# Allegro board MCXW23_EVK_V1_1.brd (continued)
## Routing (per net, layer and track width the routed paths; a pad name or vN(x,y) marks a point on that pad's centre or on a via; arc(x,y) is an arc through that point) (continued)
P5VA: length 15.1
  TOP w0.2: 14,41.54 L6.1 13.41,40.95
  TOP w0.25: v1(32.5,55) C64.1 31.74,56.2 31.44,56.5 C65.1 30,56.5 29.48,55.98 U19.8 ; R66.2 v1(43.75,71) ; U17.5 37.9,60.15 38.45,60.7 C61.1 v1(39.25,59.75) ; L6.1 14.49,40.95 15.04,41.5 C54.1 ; R72.2 v1(43.75,67)
  IN2 w0.5: v1(39.25,59.75) 38.25,60.75
  vias: v1(13.75,42.25) v1(14.75,42.25)
VBAT_DCDC/VBAT_PMU: length 15.1
  TOP w0.2: C37.1 60.09,19.3 ; C37.1 58.41,19.3 ; C37.1 59.25,20.04 ; 57.75,19.64 C36.1 58.37,19 ; 57,20 56.75,20 56.75,19.5 ; 56,20.25 U9.49 56,22.25 56.74,22.99 ; 56.75,23 56.74,22.99 ; 56.74,22.99 U9.51 ; 60.31,19.22 L2.2 61,19.94 ; U9.50 56.99,21.27 ; U9.50 56.51,20.2 ; U9.50 56.51,22.34 ; U9.51 59.3,22.99 ; U9.51 58.23,22.51
  TOP w0.25: C35.1 56.75,19.5
VBUS: length 144.4
  TOP w0.2: U11.3 30.45,11.49 ; U11.3 30.45,9.81 ; U11.3 31.07,10.65 ; 17.01,75.05 U30.1 ; U30.1 17.85,74.43 ; U30.1 18.69,75.05 ; U30.3 17.85,77.57 ; U30.3 17.01,76.95 ; U30.3 18.69,76.95 ; 18.04,79 C90.2 17.3,78.16 ; D18.A 22.43,9.5 ; D18.A 21.64,8.56 ; D18.A 20.85,9.5 ; D18.A 21.64,10.44 ; 30.5,9.29 BD1.2 29.66,8.55 ; 27.66,8.55 C50.2 ; C50.2 29.34,8.55 ; C50.2 28.5,9.29 ; 27.93,10.65 U11.1 ; U11.1 28.55,9.81 ; U11.1 28.55,11.49
  TOP w0.25: R63.1 v1(48,15.5)
  BOTTOM w0.5: v1(19.5,79) v1(18.5,79) 16.5,79 13.75,76.25 13.75,46.5 3,35.75 3,11.74 6.24,8.5 v1(23.5,8.5) v1(24.75,8.5) v1(26,8.5) v1(27.25,8.5) 41.14,8.5 48,15.36 v1(48,15.5)
VCC_IF_LINK: length 109.9
  TOP w0.25: U28.6 73.1,95.19 73,95.09 C81.1 72.5,94.5 72,95 v1(72,95.75) ; v1(68,95.75) 68,95 68.5,94.5 C74.1 69,95.06 69.1,95.16 U25.6 ; R104.1 v1(69,100.5) ; U27.6 65.1,95.16 65,95.06 C78.1 64.48,94.5 64,94.98 v1(64,95.75) ; v1(71.75,100.5) 71.75,99.76 72.01,99.5 R112.1 ; L7.1 v1(59,95.75) ; C77.1 61,94.52 ; 61,94.52 60.25,94.52 60,94.77 v1(60,95.75) ; 61,94.52 61,95.06 61.1,95.16 U26.6 ; R42.1 v1(31.5,42.25) ; v1(42,85.5) v1(42,75) ; R108.1 v1(65,100.5)
  BOTTOM w0.25: v1(42,85.5) 42.75,85.5 43.5,84.75 45.5,84.75 47.5,86.75 47.5,90.68 48.82,92 57,92 57.25,91.75 59.26,91.75 60,92.49 v1(60,95.75) ; v1(31.5,42.25) 31.5,50.49 41.5,60.49 41.5,74.5 v1(42,75)
VCC_MIKROE: length 109.2
  TOP w0.25: R30.1 v1(86,77.25) ; R29.1 v1(86,38.25) ; 86,108.12 R37.1
  TOP w0.5: v1(86,107.5) 86,108.12
  IN2 w0.5: v1(86,38.25) 82.75,41.5 82.75,46.51 80.5,48.76 80.5,54 ; v1(86,107.5) 87.25,106.25 87.25,96.5 83.25,92.5 83.25,80 v1(86,77.25) 86,74 84.5,72.5 84.5,61.62 83.25,60.37 83.25,56.75 80.5,54 ; 80.5,54 60.23,54 v2(56.49,57.74)
  BOTTOM w0.5: v2(56.49,57.74) 56.49,58.81 56.5,58.82 J16.2
ADC0_CH1_CURR: length 64.5
  TOP w0.25: TP7.1 R82.2 27.7,48.24 28,47.94 R84.2 C66.1 28,45.96 28.5,45.46 28.5,43.88 ; U9.57 v1(56.75,26) ; v1(45.75,28.5) U9.14 ; 28.5,43.88 30.25,42.13 30.25,37.24 27.25,34.24 v1(27.25,30.5) ; 28.5,43.88 28.47,43.85 U20.E 26.18,43.85 25.56,43.23 J35.1
  BOTTOM w0.25: v1(27.25,30.5) 28.25,30.5 29,29.75 37.85,29.75 38.13,30.03 38.13,30.25 38.63,30.75 41.75,30.75 44,28.5 v1(45.75,28.5) 48.25,26 v1(56.75,26)
ADC1_CH1_V: length 56.5
  TOP w0.25: v1(27.75,28.25) 27.75,28.75 28,29 28,31.75 27.75,32 27.75,34 30.75,37 30.75,42.46 31.25,42.96 31.25,49.01 36.5,54.26 36.5,55.51 36.64,55.65 U18.E 37.45,56.05 37,56.5 C63.1 37,57.54 37.3,57.84 R76.2 TP3.1 ; v1(44.25,25.75) 44,25.75 43.75,25.5 U9.20
  BOTTOM w0.25: v1(44.25,25.75) 42.5,27.5 40.5,27.5 40.25,27.25 35.75,27.25 34.75,28.25 v1(27.75,28.25)
ARD_D2: length 2.6
  TOP w0.2: R125.1 95,48.94 94.84,49.1 J26.3
ARD_D18: length 4.1
  TOP w0.25: R126.2 95,4.92 J25.5
ARD_D19: length 4.9
  TOP w0.25: J25.6 97.96,4.5 97.25,4.5 96.75,5 R127.2
ARD_IIC_SCK: length 2.6
  TOP w0.25: J24.10 55.22,49.74 55.5,49.46 R116.1
ARD_IIC_SDA: length 2.6
  TOP w0.25: R118.1 58,48.96 57.76,49.2 J24.9
ARD_RXD: length 2.5
  TOP w0.2: R124.1 100,48.94 99.92,49.02 J26.1
ARD_SPI_LIFO: length 2.5
  TOP w0.25: J24.5 67.92,49.74 68,49.66 R120.1
ARD_SPI_LOFI: length 2.5
  TOP w0.25: J24.4 70.46,49.74 70.5,49.7 R121.1
ARD_SPI_SCK: length 2.5
  TOP w0.25: R119.1 65.5,49.62 65.38,49.74 J24.6
ARD_SPI_SS: length 2.5
  TOP w0.25: J24.3 R122.1
ARD_TXD: length 2.5
  TOP w0.2: J26.2 97.38,49.06 97.5,48.94 R123.1
BRG_I2C0_SCL: length 45.2
  TOP w0.25: v1(48.25,68.25) 48.25,66 49.75,64.5 49.75,46.75 53.75,42.75 58,42.75 58.25,42.5 58.25,37.74 57.24,36.73 U9.76 ; v1(51.75,68.25) 52,68 R101.2 53.52,68 53.61,68.09 U24.5
  BOTTOM w0.25: v1(48.25,68.25) v1(51.75,68.25)
BRG_I2C0_SDA: length 44.1
  TOP w0.25: v1(51.75,70.75) 52,71 R102.2 53.29,71 53.38,70.91 U24.4 ; U9.86 51.5,37.75 49.25,40 49.25,44.25 47.75,45.75 47.75,63.5 46,65.25 46,70.25 v1(46.5,70.75)
  BOTTOM w0.25: v1(46.5,70.75) v1(51.75,70.75)
BRG_SPI1_MISO: length 68.7
  TOP w0.25: U22.12 56.25,73 57.5,71.75 57.5,64.25 57,63.75 55.5,63.75 55.25,63.5 55.25,56.49 53.25,54.49 53.25,49.5 54.5,48.25 54.5,46.41 55.16,45.75 61.74,45.75 67.5,39.99 67.5,39.76 67.76,39.5 67.76,31.92 65.08,29.24 60.49,29.24 59.75,28.5 U9.62
BRG_SPI1_MOSI: length 64.3
  TOP w0.25: U9.60 60.25,27.5 61,28.25 65.5,28.25 68.75,31.5 68.75,40.24 61.5,47.49 v1(61.5,52) ; v1(58,52.25) 58,72 56.75,73.25 U22.13
  BOTTOM w0.25: v1(58,52.25) 60.64,52.25 60.89,52 v1(61.5,52)
BRG_SPI1_SCLK: length 61.1
  TOP w0.25: U22.14 57.25,73.5 58.5,72.25 58.5,54.76 59,54.26 59,49.25 68.25,40 68.25,31.71 65.29,28.75 60.75,28.75 60,28 U9.61
BRG_SPI1_SSEL: length 49.8
  TOP w0.25: v1(53.5,48) 52.75,48.75 52.75,54.75 54.75,56.75 54.75,63.75 55.32,64.32 56.75,64.32 57,64.57 57,71.5 55.75,72.75 U22.11 ; v1(59,42.25) 59,37.5 57,35.5 57,34.75 57.25,34.5 U9.74
  BOTTOM w0.25: v1(53.5,48) 54.5,47 54.5,46.75 v1(59,42.25)
CTRL_CAL_DISC: length 41.7
  TOP w0.2: 42.23,68.98 42.44,68.98 42.46,69
  TOP w0.25: U9.3 43.75,34 44,34.25 44,35.24 43.25,35.99 43.25,39.75 44.66,41.16 44.66,55.85 42.51,58 41.5,58 v1(40.75,58.75) ; 43,69 R227.2 ; R227.2 v1(42.75,68) ; R227.2 42.25,69 42.23,68.98 Q21.G
  BOTTOM w0.25: v1(42.75,68) 42,67.25 42,60 v1(40.75,58.75)
CTRL_CAL_R1: length 76.3
  TOP w0.25: v1(51.5,22.75) 52,22.25 U9.41 ; v1(21,18.5) 20.25,19.25 20.25,58.75 20,59 19.98,59 19.88,59.1 D20.C
  BOTTOM w0.25: v1(21,18.5) 21.75,17.75 37.25,17.75 39.24,19.74 46.25,19.74 47.26,20.75 49.5,20.75 v1(51.5,22.75)
CTRL_CAL_R2: length 82.1
  TOP w0.25: U9.42 v1(52.5,22.75) ; Q17.G 18.52,62.98 20.75,60.75 20.75,19.75 v1(22,18.5)
  BOTTOM w0.25: v1(52.5,22.75) 51.5,23.75 49.58,23.75 49.25,23.42 49.25,22.4 48.1,21.25 47,21.25 46,20.25 38.99,20.25 37.24,18.5 v1(22,18.5)
CTRL_HIGH_CURR: length 61
  TOP w0.25: 42.75,63.75 R74.1 42.44,65 42.42,64.98 Q8.G ; 42.75,63.75 42.75,62.25 42.7,62.2 ; 42.75,63.75 v1(40.75,63.75) ; v1(34.5,63.75) 34.5,64.78 34.3,64.98 Q14.G ; U9.22 45,24.5 46.5,26 46.5,30.25 45,31.75 45,35 45.5,35.5 47.25,35.5 47.5,35.75 U9.94 47.5,37.72 47.73,37.95 47.73,42.27 45.75,44.25 45.75,56.24 43.43,58.56 43.43,59.03 42.75,59.71 42.75,62.15 42.7,62.2 ; 42.7,62.2 U16.4
  BOTTOM w0.25: v1(40.75,63.75) v1(34.5,63.75)
CTRL_HIGH_CURR_DIS: length 29.1
  TOP w0.25: U9.92 48.5,38 48.25,38.25 48.25,42.49 46.25,44.49 46.25,56.5 45.25,57.5 v1(45.25,58.75) ; U16.6 41.55,59.63 41.75,59.43 v1(41.75,58.75)
  BOTTOM w0.25: v1(45.25,58.75) 44.5,59.5 42.5,59.5 v1(41.75,58.75)
CTRL_HIGH_CURR_EN: length 33.8
  TOP w0.25: v1(42.75,58.75) 42.75,58.49 45.19,56.05 45.19,40.95 43.75,39.51 43.75,36.15 44.5,35.4 44.5,32 44,31.5 U9.8 ; v1(44.25,58.75) 44.25,59.36 43.95,59.66 U16.1
  BOTTOM w0.25: v1(44.25,58.75) v1(42.75,58.75)
CURR_RANGE_SET: length 11.1
  TOP w0.25: R38.2 33.95,22.8 34.25,22.5 R39.1 v1(36,22.5) ; v1(40.25,24.5) 41.25,23.5 U9.24
  BOTTOM w0.25: v1(40.25,24.5) 38.75,24.5 38,23.75 36.5,23.75 36,23.25 v1(36,22.5)
CURR_SNS+: length 14.6
  TOP w0.5: Q24.S 29.52,72.02 30,72.5 31.86,72.5 J1.8 J1.6 J1.4 J1.2
CURR_SNS-: length 16.6
  TOP w0.5: Q26.S 33.52,72.5 34.02,73 38.62,73 39.37,73.75 J2.8 J2.6 J2.4 J2.2
DBGIF_DETECT: length 4.2
  TOP w0.25: R169.2 R168.2 U9.78
DBGIF_ISP0_CTRL: length 91.4
  TOP w0.25: U9.72 59.5,33.5 59.75,33.75 65,33.75 65.25,34 65.25,38.49 60.49,43.25 54.01,43.25 50.25,47.01 50.25,64.75 49,66 49,72 v1(48.25,72.75) ; v1(75,75.75) U23.2 75,81.25 74.75,81.5 R99.2
  BOTTOM w0.25: v1(75,75.75) 71.75,75.75 69.75,73.75 67.08,73.75 66.86,73.53 56.27,73.53 55.49,72.75 v1(48.25,72.75)
DBGIF_RESET: length 83.7
  TOP w0.25: U27.3 66.9,98.15 v1(67,98.25) ; U9.90 49.5,38 48.75,38.75 48.75,44.01 47.25,45.51 47.25,63.25 45.5,65 45.5,90.64 45.25,90.89 v1(45.25,91.75)
  BOTTOM w0.25: v1(67,98.25) 65,98.25 63.75,99.5 59.24,99.5 56.64,96.9 49.65,96.9 47.5,94.75 47.5,93.99 45.7,92.19 45.69,92.19 v1(45.25,91.75)
DBGIF_RESET_TXEN: length 106
  TOP w0.25: U27.5 v1(66,96.5) R111.1 ; U9.71 59.75,33 60,33.25 65.25,33.25 65.7,33.7 65.7,38.8 60.75,43.75 54.19,43.75 50.75,47.19 50.75,55.75 52.75,57.75 52.75,63.5 49.5,66.75 49.5,73.01 48,74.51 48,76.24 47,77.24 47,91.64 47.25,91.89 v1(47.25,92.75)
  BOTTOM w0.25: v1(47.25,92.75) 48,93.5 48,94.49 49.96,96.45 56.95,96.45 59.5,99 63.5,99 v1(66,96.5)
DBGIF_TCK_SWCLK: length 125.7
  TOP w0.25: U26.3 62.9,98.15 v1(63,98.25) ; v1(71.75,52) 71.75,43.99 70.75,42.99 70.75,28.25 65,22.5 61.24,22.5 59.24,24.5 U9.54 ; v1(46,58) 46,58.68 46.25,58.93 46.25,62.75 44.5,64.5 44.5,84.14 43.75,84.89 v1(43.75,85.5)
  BOTTOM w0.25: v1(43.75,85.5) 44.19,85.94 44.19,86.18 46.58,88.57 46.58,91.04 48.54,93 57.25,93 57.72,93.47 57.72,96.47 59.5,98.25 v1(63,98.25) ; v1(71.75,52) 62.74,52 61.74,53 51,53 v1(46,58)
DBGIF_TDO_SWO: length 98.6
  TOP w0.25: v1(45.25,92.75) 46,92 46,72.5 47.25,71.25 47.25,70 46.5,69.25 46.5,65.5 48.25,63.75 48.25,46.01 53.5,40.76 53.5,38.74 53,38.24 U9.83 ; U28.3 74.9,98.15 v1(75,98.25)
  BOTTOM w0.25: v1(45.25,92.75) 45.25,94.74 48.76,98.25 55.75,98.25 60.75,103.25 62.25,103.25 63.75,101.75 66.25,101.75 69,99 71.5,99 72.25,98.25 v1(75,98.25)
DBGIF_TMS_SWDIO: length 91.9
  TOP w0.25: v1(71,98.25) 70.9,98.15 U25.3 ; v1(46,93.5) 46.5,93 46.5,72.74 47.75,71.49 47.75,69.75 47,69 47,65.75 48.75,64 48.75,46.25 54,41 U9.81
  BOTTOM w0.25: v1(71,98.25) 69,98.25 66,101.25 64.75,101.25 64,100.5 58.76,100.5 56.06,97.8 49.05,97.8 46,94.75 v1(46,93.5)
DBGIF_TMS_SWDIO_TXEN: length 115.3
  TOP w0.25: R106.1 v1(70,96.5) U25.5 ; v1(46.75,94.25) 48,93 48,91.75 47.5,91.25 47.5,77.5 50.5,74.5 50.5,67.25 53.7,64.05 53.7,57.2 51.75,55.25 51.75,47.74 54.74,44.75 61.23,44.75 66.75,39.23 66.75,32.96 65.04,31.25 59.97,31.25 59.22,30.5 U9.66
  BOTTOM w0.25: v1(46.75,94.25) 46.75,94.86 49.24,97.35 56.35,97.35 59,100 64,100 65,99 67.5,99 v1(70,96.5)
DBGIF_VREF: length 12.4
  TOP w0.25: U9.23 41.75,24 v1(41.25,24.5) ; v1(36,24.5) C22.1 34.56,24.5 34.26,24.2 R43.1 R42.2
  BOTTOM w0.25: v1(36,24.5) 36.25,24.25 37.75,24.25 38.75,25.25 40.5,25.25 v1(41.25,24.5)
FUNC: length 69.5
  TOP w0.25: v1(5,21.5) D12.C ; U9.87 v1(51,35) ; v1(9.5,37.5) 11.75,35.25 11.75,29.5 8.5,26.25 v1(8.5,21.5)
  BOTTOM w0.25: v1(9.5,37.5) 10.26,37.5 10.51,37.75 38.99,37.75 40.99,39.75 46.99,39.75 51,35.74 v1(51,35) ; v1(8.5,21.5) v1(5,21.5)
HW_VER_0: length 3.9
  TOP w0.25: R47.1 50.5,39.5 52,38 U9.85
HW_VER_1: length 4
  TOP w0.25: U9.73 59.25,34 59.75,34.5 R48.1
HW_VER_2: length 110.2
  TOP w0.25: U24.3 54.5,71.65 54.52,71.67 Q11.G 51.98,72.48 51,71.5 51,67.51 54.25,64.26 54.25,56.99 52.25,54.99 52.25,48.02 55.02,45.25 61.5,45.25 67.05,39.7 67.05,39.57 67.25,39.37 67.25,32.75 65.25,30.75 60.25,30.75 59.5,30 U9.65 v1(56.75,30)
  BOTTOM w0.25: J28.1 18.83,35 20.08,36.25 46.5,36.25 49,33.75 53,33.75 v1(56.75,30)
HW_VER_3: length 3.8
  TOP w0.25: R49.1 39.56,35 39.57,35.01 U9.1
HW_VER_4: length 3.8
  TOP w0.25: R50.1 U9.31
HW_VER_5: length 3.8
  TOP w0.25: U9.5 R51.1
HW_VER_6: length 113.7
  TOP w0.25: v1(66,27.75) 69.25,31 69.25,40.5 64,45.75 64,51.5 62.63,52.87 61.13,52.87 59,55 59,72.25 60,73.25 62.75,73.25 63.5,74 63.5,76.25 63.23,76.52 Q10.G ; U9.56 57.25,25.5 v1(56.75,25)
  BOTTOM w0.25: J29.1 19.25,29 19.75,29.5 28.49,29.5 28.74,29.25 37.99,29.25 38.99,30.25 41.5,30.25 44,27.75 45.49,27.75 48.24,25 48.73,25 48.88,25.15 53.12,25.15 53.27,25 v1(56.75,25) 59.5,27.75 v1(66,27.75)
HW_VER_7: length 140.6
  TOP w0.25: v1(27.25,20.5) 27.25,26.75 25.75,28.25 25.75,34.01 29.5,37.76 v1(29.5,39.5) ; v1(48,43.75) 46.75,45 46.75,63 45,64.75 45,84.64 44.75,84.89 v1(44.75,85.5) ; U26.5 60.25,96.5 v1(60,96.75) ; v1(44.75,22.75) 45,22.5 U9.27
  BOTTOM w0.25: v1(44.75,22.75) 44.25,22.25 37.99,22.25 36.49,20.75 32.49,20.75 31.99,21.25 31,21.25 30.25,20.5 v1(27.25,20.5) 20.27,20.5 J30.1 ; v1(44.75,85.5) 47.04,87.79 47.04,90.86 48.68,92.5 57.5,92.5 58.25,93.25 58.25,96.25 58.75,96.75 v1(60,96.75) ; v1(48,43.75) 48,43.04 46.21,41.25 40.26,41.25 38.51,39.5 v1(29.5,39.5)
HW_VER_8: length 4.5
  TOP w0.25: R46.1 61.2,23.25 59.45,25 U9.55
LED_NRG: length 61.6
  TOP w0.25: U9.64 57.25,29.5 v1(56.75,29) ; v1(5,30.5) D14.C ; v1(9.5,33.5) v1(9.5,31)
  BOTTOM w0.25: v1(5,30.5) 5.5,31 v1(9.5,31) ; v1(9.5,33.5) 9.75,33.25 19.01,33.25 20.94,35.18 35.28,35.18 35.46,35 35.5,35 35.75,34.75 37.74,34.75 38.67,35.68 46.33,35.68 48.76,33.25 52.5,33.25 v1(56.75,29)
LED_SIO: length 69.7
  TOP w0.25: v1(5,33.5) D13.C ; v1(6.5,18.75) v1(6.5,33.5) ; U9.43 53,22.25 v1(53.5,22.75)
  BOTTOM w0.25: v1(53.5,22.75) 52,24.25 49.26,24.25 48.75,23.74 48.75,22.54 47.96,21.75 46.74,21.75 45.74,20.75 38.75,20.75 37.25,19.25 7,19.25 v1(6.5,18.75) ; v1(6.5,33.5) v1(5,33.5)
LED_SWO_ACT: length 58.2
  TOP w0.25: v1(36,35.5) 36,34.89 36.64,34.25 39.3,34.25 39.55,34.5 U9.2 ; v1(9.5,34.5) 10.25,33.75 10.25,30.75 7.25,27.75 7.25,17.75 5,15.5 D9.C
  BOTTOM w0.25: v1(9.5,34.5) 10.25,33.75 18.76,33.75 20.76,35.75 35.35,35.75 35.6,35.5 v1(36,35.5)
LED_USB_COMM: length 65.5
  TOP w0.25: v1(9.5,35.5) 10.75,34.25 10.75,30.25 v1(8,27.5) ; U9.67 v1(56.75,31) ; v1(5,27.5) D8.C
  BOTTOM w0.25: v1(9.5,35.5) 10.24,35.5 11.49,36.75 46.75,36.75 49.25,34.25 53.5,34.25 v1(56.75,31) ; v1(8,27.5) v1(5,27.5)
LED_VCOM_ACT: length 70.6
  TOP w0.25: v1(9.25,24.5) 9.25,26.25 12.25,29.25 12.25,35.75 v1(9.5,38.5) ; U9.82 v1(53.5,35) ; D11.C v1(5,24.5)
  BOTTOM w0.25: v1(53.5,35) 52.51,35 47.26,40.25 40.74,40.25 38.74,38.25 10.51,38.25 10.26,38.5 v1(9.5,38.5) ; v1(5,24.5) v1(9.25,24.5)
LPC_P1_7-MCULINK: length 58
  TOP w0.25: J27.6 44,4.44 44,6.25 43.5,6.75 40.75,6.75 35.5,12 35.5,13.26 28,20.76 28,27 26.5,28.5 v1(26.5,33.75) ; U9.9 41.78,31 41.5,31.28 41.5,31.5 40.75,32.25 36,32.25 v1(35.25,31.5)
  BOTTOM w0.25: v1(26.5,33.75) 27.11,33.75 29.36,31.5 v1(35.25,31.5)
LPC_P1_20-MCULINK: length 51.5
  TOP w0.25: U9.4 39.55,33.5 39.3,33.75 36.75,33.75 v1(36,33) ; J27.5 43.73,7.25 41,7.25 36,12.25 36,13.5 28.5,21 v1(28.5,33.75)
  BOTTOM w0.25: v1(28.5,33.75) 29.25,33 v1(36,33)
LPC_P1_21-MCULINK: length 45.5
  TOP w0.25: U9.30 46.5,22.29 46.04,22.75 v1(45.75,22.75) ; J27.2 49,4.52 49,6.75 47,8.75 41.63,8.75 37.5,12.88 37.5,14.5 v1(31.5,20.5)
  BOTTOM w0.25: v1(31.5,20.5) 31.75,20.25 36.75,20.25 38.25,21.75 44.75,21.75 v1(45.75,22.75)
LPC_P1_31-MCULINK: length 63
  TOP w0.25: U9.91 49,35.25 48.25,34.5 v1(46.5,34.5) ; J27.4 46.5,4.48 46.5,6.5 45.25,7.75 41.21,7.75 36.5,12.46 36.5,13.74 29,21.24 29,32.75 29.75,33.5 v1(29.75,34.5)
  BOTTOM w0.25: v1(46.5,34.5) 45.5,34.5 45.25,34.25 35.25,34.25 35,34.5 v1(29.75,34.5)
LPC_PIO0_5-ISP_EN-LED_SWD_ACT: length 92.9
  TOP w0.25: R57.1 11.95,49.55 12.25,49.25 12.25,45.26 8.75,41.76 8.75,37.29 9.5,36.54 v1(9.5,36.5) 11.25,34.75 11.25,29.75 7.75,26.25 7.75,18.25 v1(8,18) ; R57.1 11,53.17 11.5,53.67 J32.1 ; R57.1 10.05,49.55 9.75,49.25 9.75,48.69 9.56,48.5 R55.2 ; U9.88 50.5,35.5 v1(50,35) ; v1(5,18.5) D10.C
  BOTTOM w0.25: v1(50,35) 47.75,37.25 11,37.25 10.25,36.5 v1(9.5,36.5) ; v1(5,18.5) 5.5,18 v1(8,18)
LPC_PIO0_10-SWO: length 64.2
  TOP w0.25: J31.6 R52.2 8,44.25 7.25,43.5 v1(7.25,30.25) ; U9.21 44.5,25 v1(45.25,25.75)
  BOTTOM w0.25: v1(7.25,30.25) 9.99,27.51 18.51,27.51 20,29 28.25,29 28.5,28.75 38.25,28.75 39.25,29.75 41.25,29.75 43.75,27.25 44.74,27.25 45.25,26.74 v1(45.25,25.75)
LPC_PIO0_11-SWDCLK: length 60.1
  TOP w0.25: v1(8,32) 8,36.76 7.75,37.01 7.75,42.32 8,42.57 v1(8,43.25) ; R60.1 v1(7,46) 6.73,46.27 J31.4 ; v1(45,29.25) 44.39,29.25 44.14,29 U9.13
  BOTTOM w0.25: v1(7,46) 8,45 v1(8,43.25) ; v1(8,32) 9.01,32 9.26,32.25 27.33,32.25 29.28,30.3 35.8,30.3 36.75,31.25 42,31.25 44,29.25 v1(45,29.25)
LPC_PIO0_12-SWDIO: length 58.6
  TOP w0.25: R53.2 v1(7,47) 6.25,47 5.71,47.54 J31.2 ; v1(44.25,30) 43.75,29.5 U9.12 ; v1(8.75,32.75) 8.75,36.65 8.25,37.15 8.25,42 8.75,42.5 v1(8.75,44)
  BOTTOM w0.25: v1(8.75,44) 8.75,45.25 v1(7,47) ; v1(8.75,32.75) 27.47,32.75 29.47,30.75 35.61,30.75 36.56,31.7 42.55,31.7 v1(44.25,30)
MCU_LINK_3V3: length 56.4
  TOP w0.25: U9.44 53.5,20.25 v1(53.25,20) ; v1(40,22.99) 39.57,22.99 39.56,23 C27.1 ; v1(40,22.99) 40,22.5 37.75,20.25 33.75,20.25 33.5,20.5 R38.1 ; v1(40,22.99) 40,23.75 39.75,24 C32.1 ; v1(40,22.99) U9.25 ; C33.1 v1(60.5,32) U9.69 ; v1(46.5,39) 47,38.5 U9.95 ; v1(46.5,39) C30.1 ; v1(46.5,39) U9.96 ; U9.63 59.5,29 v1(60.5,30) C29.1 ; U9.75 59.51,35.01 v1(60.5,36) C24.1 ; 39.75,30.5 39.75,30 v1(40.75,29) 41.75,28 U9.15 ; 39.75,30.5 39.75,31.31 39.56,31.5 C26.1 ; 39.75,30.5 C31.1 ; C49.1 53.25,16.25 53,16.5 v1(53,17.25) C48.1 ; C28.1 50,18.21 50.75,18.96 v1(50.75,19.25) 50.5,19.5 U9.38 ; U9.100 v1(44.49,38.99) ; U9.84 52.5,38.14 52.25,38.39 v1(52.25,39) 51.75,39 51.5,39.25 C34.1 ; L1.2 39.5,39.01 39.3,38.81 C25.1 v1(40.5,38)
MCU_LINK_N_16MHZ: length 10.3
  TOP w0.25: U9.28 45.5,20.25 45.25,20 43.25,20 43,19.75 43,16.49 42.59,16.08 Y1.1 41.17,16.08 40.75,16.5 C47.1
MCU_LINK_P_16MHZ: length 6.7
  TOP w0.25: U9.29 46,20 45.5,19.5 44.5,19.5 44.15,19.15 Y1.3 45.04,17.92 45.46,17.5 C46.1
MCU_LINK_RST: length 67.9
  TOP w0.25: v1(47,22.75) 47.5,22.25 U9.32 ; v1(5.75,19.5) 5.75,40.85 J31.10
  BOTTOM w0.25: v1(5.75,19.5) 6.51,19.5 6.76,19.75 37.01,19.75 38.51,21.25 45.5,21.25 v1(47,22.75)
MCU_LNK_RX: length 85.7
  TOP w0.25: v1(48.75,75.25) 50,74 50,67.01 53.25,63.76 53.25,57.49 51.25,55.49 51.25,47.5 54.5,44.25 61.01,44.25 66.25,39.01 66.25,33.5 65.5,32.75 60.25,32.75 60,32.5 U9.70 ; U21.13 68.25,75.75 v1(69,75)
  BOTTOM w0.25: v1(48.75,75.25) 53.51,75.25 54.26,74.5 66.25,74.5 66.75,75 v1(69,75)
MCU_LNK_TX: length 67.3
  TOP w0.25: U21.14 68.75,76 69,75.75 69.25,75.75 v1(70,75) ; v1(47.25,74.5) 47.25,72.74 48.25,71.74 48.25,69.5 47.5,68.75 47.5,66 49.25,64.25 49.25,46.49 54.5,41.24 54.5,38.75 55,38.25 U9.79
  BOTTOM w0.25: v1(47.25,74.5) 53.5,74.5 54,74 66.69,74 66.94,74.25 69.25,74.25 v1(70,75)
MCULINK_VDDA: length 27.3
  TOP w0.25: U9.16 40.5,27.5 v1(40,28) ; v1(40,28) 40,28.68 39.68,29 C40.1 ; v1(40,28) C39.1 ; v1(37,25) R62.1 ; L3.2 v1(41.5,38.75)
  IN2 w0.5: v1(40,28) 38.5,28 ; 38.5,28 38.5,25.72 37.78,25 v1(37,25) ; 38.5,28 38.5,38.25 39.56,39.31 40.94,39.31 v1(41.5,38.75)
Net_3: length 44.3
  TOP w0.25: 58.23,31.5 57.25,31.5 v1(56.75,32)
  BOTTOM w0.25: v1(56.75,32) 56.75,33 53.5,36.25 52.01,36.25 47.51,40.75 40.49,40.75 38.49,38.75 20.25,38.75 v1(19.5,39.5)
NFC_3V0: length 169.4
  TOP w0.25: R155.2 v1(102.5,28.75) ; v1(81.25,104.25) v1(81.25,67.75) 81.25,56.99 86,52.24 86,50.24 82.5,46.74 82.5,42.24 81.75,41.49 81.75,35.5 81,34.75 v1(81,28.75) ; R154.2 v1(102.5,67.75)
  BOTTOM w0.25: v1(102.5,67.75) v1(81.25,67.75) ; v1(81.25,104.25) 69.75,104.25 65.7,108.3 44.31,108.3 44.3,108.31 J4.2 ; v1(102.5,28.75) v1(81,28.75)
P1_1-MCULINK: length 144.2
  TOP w0.25: v1(68,27.75) 70.25,30 70.25,43 69.25,44 69.25,51.74 67.22,53.77 61.73,53.77 60,55.5 60,71.75 60.5,72.25 67.31,72.25 68,72.94 R91.1 ; v1(30.75,33.75) 30.75,32.24 30.25,31.74 30.25,23.5 32.25,21.5 32.25,20.99 38,15.24 38,13.09 41.84,9.25 48,9.25 50.29,6.96 J27.1 ; v1(56.75,27.5) 57.25,27 U9.59
  BOTTOM w0.25: v1(68,27.75) 66.75,29 59.26,29 57.76,27.5 v1(56.75,27.5) 51.5,32.75 48.5,32.75 47.5,33.75 v1(30.75,33.75)
P1_9-MCULINK: length 140.7
  TOP w0.25: R92.1 67,72.94 66.81,72.75 66,72.75 ; J27.3 47.75,7 46.5,8.25 41.42,8.25 37,12.67 37,14 29.75,21.25 v1(29.75,32.25) ; 66,72.75 60.25,72.75 59.5,72 59.5,55.28 61.46,53.32 64.94,53.32 66.75,51.51 66.75,44.51 69.75,41.51 69.75,30.5 v1(67,27.75) ; 66,72.75 R88.2 ; U9.10 43.75,30.5 44,30.75 v1(45,30.75)
  BOTTOM w0.25: v1(67,27.75) 66.25,28.5 59.49,28.5 57.74,26.75 49,26.75 v1(45,30.75) 43.5,32.25 v1(29.75,32.25)
PIO0_0-FC0_CTS_SDA_SSEL0: length 142.6
  TOP w0.25: J12.10 70.12,108.62 v1(70,108.5) ; v1(79.5,35.25) v1(79.5,45.5) 79.5,46.74 80,47.24 80,55 78.25,56.75 v1(78.25,86.5) 78.25,100.76 79,101.51 79,106.89 79.5,107.39 v1(79.5,108) ; R122.2 v1(73,45.5) ; v1(55,85) R97.2 ; R149.1 v1(97.5,35.25)
  BOTTOM w0.25: v1(97.5,35.25) v1(79.5,35.25) ; v1(70,108.5) 70.5,108 v1(79.5,108) ; v1(55,85) 57,85 58.5,86.5 v1(78.25,86.5) ; v1(79.5,45.5) v1(73,45.5)
PIO0_1: length 142.1
  TOP w0.2: R125.2 v1(96.25,46.7)
  TOP w0.25: 70.5,61.25 65.29,61.25 J13.3 ; 70.5,61.25 70.5,63.5 71.75,64.75 76.5,64.75 77.25,65.5 77.25,73.75 76.75,74.25 76.75,90 77.25,90.5 77.25,101.5 77.5,101.75 77.5,102.5 78.25,103.25 78.25,104.5 77.93,104.82 J12.3 ; 70.5,61.25 70.5,58.75 71,58.25 76,58.25 79.5,54.75 79.5,47.5 v1(78.75,46.75) v1(78.75,28) ; R156.2 v1(100,28)
  BOTTOM w0.25: v1(96.25,46.7) 95.64,46.7 95.59,46.75 v1(78.75,46.75) ; v1(100,28) v1(78.75,28)
PIO0_2-FC0_RXD_SDA_MOSI: length 251.4
  TOP w0.2: v1(101.25,46.75) 101.2,46.7 R124.2
  TOP w0.25: v1(76.73,102.25) 76.12,102.25 75.81,102.56 J12.1 ; R152.1 v1(90,37.5) ; J13.7 69.12,58.88 70.25,57.75 75.75,57.75 76.75,56.75 76.75,49.61 78,48.36 v1(78,44) v1(78,37.5) v1(78,26.5) 78,9.5 79,8.5 94.5,8.5 95,8 R126.1 ; v1(73,64) 76.49,64 77.7,65.21 77.7,74.55 77.5,74.75 v1(77.5,85) v1(77.5,89) 77.5,90 77.75,90.25 77.75,101.07 78.25,101.57 v1(78.25,102.25) ; R118.2 58.95,46.7 59,46.75 v1(59.25,46.75) ; v1(97.5,26.5) R157.2 ; R160.2 v1(90,26.5) ; R121.2 v1(70.5,45.5) ; v1(57,83.5) R96.2
  BOTTOM w0.25: v1(78,26.5) v1(90,26.5) v1(97.5,26.5) ; J36.1 51.17,84.75 53.01,84.75 54.26,83.5 v1(57,83.5) 58.5,85 v1(77.5,85) ; v1(73,64) 73,62 72.38,61.38 70.5,61.38 J13.7 ; J19.10 72.58,89 v1(77.5,89) ; v1(76.73,102.25) v1(78.25,102.25) ; v1(78,37.5) v1(90,37.5) ; v1(59.25,46.75) 65.5,46.75 67.5,44.75 69.75,44.75 v1(70.5,45.5) 72,44 v1(78,44) 81.01,44 82.26,45.25 99.75,45.25 v1(101.25,46.75)
PIO0_3-FC0_TXD_SCL_MISO: length 263.5
  TOP w0.2: v1(98.75,46.75) 98.7,46.7 R123.2
  TOP w0.25: R120.2 v1(68,45.5) ; v1(70,114.25) 70,113.95 70.25,113.7 J12.18 ; R116.2 56.45,46.7 56.75,47 v1(56.75,47.5) ; R127.1 96.75,8.5 96,9.25 79.25,9.25 78.75,9.75 78.75,25.75 v1(80.25,27.25) v1(80.25,36.75) v1(80.25,44.75) 80.25,46.85 80.5,47.1 80.5,55.14 80.25,55.39 80.25,55.75 79,57 v1(79,58.5) v1(79,85.75) v1(79,90.25) 79,100.76 79.75,101.51 79.75,106.75 80.25,107.25 80.25,113.89 80,114.14 80,114.25 v1(79.5,114.75) ; v1(56,84.25) R95.2 ; v1(95,27.25) R158.2 ; R159.2 v1(92.5,27.25) ; R151.1 v1(92.5,36.75)
  BOTTOM w0.25: J36.3 54.21,84.25 v1(56,84.25) 57,84.25 58.5,85.75 v1(79,85.75) ; J13.11 75.7,58.5 v1(79,58.5) ; v1(92.5,36.75) v1(80.25,36.75) ; v1(98.75,46.75) 98,46 81.5,46 v1(80.25,44.75) 72.75,44.75 71.32,46.18 68.68,46.18 v1(68,45.5) 66,47.5 v1(56.75,47.5) ; v1(70,114.25) 70.61,114.25 70.86,114.5 78.57,114.5 78.82,114.75 v1(79.5,114.75) ; J19.12 74.91,90.27 74.93,90.25 v1(79,90.25) ; v1(80.25,27.25) v1(92.5,27.25) v1(95,27.25)
PIO0_4-FC0_SCK: length 140
  TOP w0.25: R94.2 v1(58,83.5) ; 81,35.39 v1(81,36) v1(81,43.25) 81,55.76 79.75,57.01 v1(79.75,84.25) 79.75,100.75 80.5,101.5 v1(80.5,103.5) ; v1(70,103.5) 70.61,103.5 70.65,103.54 J12.2 ; R150.1 v1(95,36) ; R119.2 v1(65.5,45.5)
  BOTTOM w0.25: v1(65.5,45.5) 67.75,43.25 v1(81,43.25) ; v1(79.75,84.25) 58.75,84.25 v1(58,83.5) ; v1(95,36) v1(81,36) ; v1(80.5,103.5) v1(70,103.5)
PIO0_5-FC2_CTS_SDA_SSEL0: length 25.1
  TOP w0.25: v1(78.25,109.75) 78,110 77.63,110 77.53,109.9 J12.11 ; R142.1 v1(97.5,106.5)
  BOTTOM w0.25: v1(97.5,106.5) 94.01,106.5 91.51,109 80.75,109 80,109.75 v1(78.25,109.75)
PIO0_6-FC2_RXD_SDA_MOSI-SPIFI_IO0: length 74.5
  TOP w0.25: v1(84.25,96.25) 84.25,105.5 v1(83,106.75) 81.5,108.25 v1(81.5,110.75) ; v1(97.5,96.25) R130.2 ; v1(78.25,111.25) 78,111.25 77.91,111.16 J12.13 ; R145.1 v1(90,106.75) ; R133.2 v1(90,96.25)
  BOTTOM w0.25: v1(81.5,110.75) 81,111.25 v1(78.25,111.25) ; v1(83,106.75) v1(90,106.75) ; v1(97.5,96.25) v1(90,96.25) v1(84.25,96.25) 79.5,96.25 78.5,95.25 72.99,95.25 72.49,94.75 63.01,94.75 62,93.74 62,91.12 J19.2
PIO0_7-FC2_TXD_SCL_MISO-SPIFI_IO1: length 79.2
  TOP w0.25: v1(70,111.25) 70.25,111.25 70.34,111.16 J12.14 ; v1(95,95.5) R131.2 ; R132.2 v1(92.5,95.5) ; R144.1 v1(92.5,106) ; v1(85,95.5) 85,105.75 v1(84.75,106) 82.5,108.25 v1(82.5,110.75)
  BOTTOM w0.25: v1(70,111.25) 76.89,111.25 77.64,112 81.25,112 v1(82.5,110.75) ; v1(84.75,106) v1(92.5,106) ; v1(95,95.5) v1(92.5,95.5) v1(85,95.5) 79.5,95.5 78.75,94.75 73.25,94.75 72.79,94.29 69.28,94.29 68.32,93.33 64.83,93.33 63.69,92.19 J19.4
PIO0_8-SPIFI_IO2: length 48.8
  TOP w0.25: J12.19 77.98,114.98 78.25,115.25 v1(78.25,116.5) ; R128.2 102.5,95.25 101.25,96.5 v1(101.25,115.25)
  BOTTOM w0.25: v1(101.25,115.25) 100.5,116 78.75,116 v1(78.25,116.5)
PIO0_9-SPIFI_IO3: length 53.1
  TOP w0.25: R129.2 100,104.25 98.75,105.5 v1(98.75,115.25) ; J12.20 70.27,114.98 v1(70,115.25)
  BOTTOM w0.25: v1(70,115.25) 70.61,115.25 70.86,115 78.24,115 78.72,115.48 97.91,115.48 98.14,115.25 v1(98.75,115.25)
PIO0_10-FC2_SCK: length 30.2
  TOP w0.25: J12.12 70.35,109.9 v1(70,110.25) ; R143.1 v1(95,107.25)
  BOTTOM w0.25: v1(70,110.25) 70.61,110.25 70.86,110.5 80,110.5 81,109.5 91.75,109.5 94,107.25 v1(95,107.25)
PIO0_11-SWDCLK: length 47.2
  TOP w0.25: J11.4 v1(49.27,118.52) 49,118.25 ; v1(66.25,113.5) 66.25,101.75 65.68,101.18 62.93,101.18 62,100.25 R109.2 ; 49,118.25 47.75,118.25 47.5,118 R24.2 ; 49,118.25 D6.C ; J8.16 v1(57.06,112.44)
  BOTTOM w0.25: v1(66.25,113.5) 65,113.5 64,112.5 57.73,112.5 57.67,112.44 v1(57.06,112.44) 56.25,113.25 56.25,115.72 54.72,117.25 50.54,117.25 v1(49.27,118.52)
PIO0_12-SWDIO: length 43.9
  TOP w0.25: 50.54,118.25 50.54,117.85 50.5,117.81 R23.1 ; 50.54,118.25 v1(50.54,118.5) J11.2 ; 50.54,118.25 51.75,118.25 52,118 D7.C ; R105.2 70,100.76 67.75,103.01 v1(67.75,113.5) ; J8.18 v1(57.05,113.7)
  BOTTOM w0.25: 57.05,114.31 57.05,115.56 54.86,117.75 51.29,117.75 v1(50.54,118.5) ; 57.05,114.31 v1(57.05,113.7) ; 57.05,114.31 57.3,114.31 57.36,114.25 67,114.25 v1(67.75,113.5)
PIO0_13-FC1_RXD_SDA_MOSI: length 138.7
  TOP w0.25: v1(56.25,70.75) 56.09,70.91 U24.1 ; v1(80.5,105.75) 82.24,105.75 82.75,105.24 v1(82.75,94.25) 82.75,91.29 82.24,90.78 82.24,81.01 82.75,80.5 v1(82.75,76.5) v1(82.75,65.5) v1(82.75,61.25) ; v1(97.5,65.5) R135.2 ; R141.1 v1(90,76.5) ; R134.2 v1(90,65.5) ; J12.5 77.92,106.08 v1(78.25,105.75)
  BOTTOM w0.25: v1(82.75,94.25) 73.79,94.25 71.79,92.25 69.99,92.25 69.49,91.75 67.71,91.75 J19.6 ; v1(90,76.5) v1(82.75,76.5) 78.25,76.5 76.75,75 71.64,75 69.89,73.25 67.22,73.25 66.98,73.01 56.51,73.01 56.25,72.75 v1(56.25,70.75) ; v1(80.5,105.75) v1(78.25,105.75) ; v1(82.75,61.25) 72.91,61.25 J13.9 ; v1(97.5,65.5) v1(90,65.5) v1(82.75,65.5)
PIO0_14-FC1_TXD_SCL_MISO: length 140.4
  TOP w0.25: v1(82,105) v1(82,91.75) 82,91.18 81.75,90.93 81.75,80.5 82,80.25 v1(82,75.75) v1(82,66.25) v1(82,60) ; U24.8 56.09,68.09 v1(56.25,68.25) ; R137.2 v1(92.5,66.25) ; R140.1 v1(92.5,75.75) ; J12.4 70.18,104.82 v1(70,105) ; R136.2 v1(95,66.25)
  BOTTOM w0.25: v1(82,66.25) v1(92.5,66.25) v1(95,66.25) ; J13.13 v1(82,60) ; v1(92.5,75.75) v1(82,75.75) 78.25,75.75 77,74.5 72,74.5 70.25,72.75 67.36,72.75 67.11,72.5 57.25,72.5 57,72.25 57,69 v1(56.25,68.25) ; v1(82,91.75) 70.25,91.75 J19.8 ; v1(82,105) v1(70,105)
PIO0_15-FC1_CTS_SDA_SSEL0: length 65
  TOP w0.25: v1(79.5,113.25) 78.69,112.44 J12.15 ; R138.1 v1(97.5,74.25) ; v1(84.75,110.75) 84.75,107.75 86.5,106 86.5,93 86,92.5 86,83.33 86.13,83.2 86.13,82.52 85,81.39 v1(85,74.25)
  BOTTOM w0.25: v1(79.5,113.25) 82.25,113.25 v1(84.75,110.75) ; v1(97.5,74.25) v1(85,74.25)
PIO0_16-FC1_SCK: length 69.3
  TOP w0.25: R139.1 v1(95,75) ; v1(84.25,75) 84.25,81 83.25,82 83.25,90.51 85.75,93.01 85.75,105.99 83.75,107.99 v1(83.75,110.75) ; J12.16 70.19,112.44 v1(70,112.25)
  BOTTOM w0.25: v1(83.75,110.75) 82,112.5 77.5,112.5 77.25,112.25 v1(70,112.25) ; v1(84.25,75) v1(95,75)
PIO0_17-SWO: length 62.8
  TOP w0.25: J11.6 48,120.25 v1(46.25,118.5) 46,118.25 ; D5.C 46,118.25 ; 46,118.25 44.76,118.25 44.5,117.99 R22.1 ; J12.17 77.8,113.7 v1(78.25,113.25) ; R114.2 74,99.52 72.27,101.25 70.25,101.25 68.5,103 v1(68.5,112)
  BOTTOM w0.25: v1(78.25,113.25) 77.61,113.25 77.36,113 69.5,113 v1(68.5,112) 65,112 64.75,111.75 56.21,111.75 55.75,112.21 55.75,115.58 54.58,116.75 48,116.75 v1(46.25,118.5)
PIO0_18-FC2_RXD_SDA_MOSI: length 150
  TOP w0.25: R21.2 v1(6.5,61) ; J36.5 52.75,88.25 50.75,88.25 50.25,88.75 50.25,90.51 52.24,92.5 56.74,92.5 57.75,93.51 57.75,100.76 55.75,102.76 55.75,109.25 v1(55,110) ; v1(70,107.5) 70.14,107.36 J12.8
  BOTTOM w0.25: 55,108.75 66,108.75 67.25,107.5 v1(70,107.5) ; 55,108.75 v1(55,110) ; 55,108.75 44.5,108.75 43.75,109.5 37.26,109.5 36.26,108.5 9.25,108.5 7.25,106.5 7.25,79.75 4.75,77.25 4.75,71.75 7.25,69.25 7.25,61.75 v1(6.5,61)
PIO0_19-FC2_TXD_SCL_MISO: length 77.5
  TOP w0.25: v1(91.25,108.25) 91.25,109 91,109.25 91,114 90.75,114.25 R14.1 90.75,115.54 90.54,115.75 90.5,115.75 90.23,116.02 Q1.G ; J12.9 77.91,108.62 78.04,108.75 v1(78.25,108.75) ; J36.7 55.29,88.25 53.69,88.25 52.75,89.19 52.75,90.5 54.25,92 57,92 58.2,93.2 58.2,100.95 56.25,102.9 56.25,109.75 v1(56,110)
  BOTTOM w0.25: v1(91.25,108.25) 80.76,108.25 80.26,108.75 v1(78.25,108.75) 71.25,108.75 70.75,109.25 56.75,109.25 v1(56,110)
PIO0_20-ISP: length 125.1
  TOP w0.25: D17.A v1(62.5,82.5) ; R15.2 v1(6.5,77) ; R100.2 v1(76,82.5) 76,90.01 76.75,90.76 76.75,100 76.25,100.5 73.75,100.5 72.5,101.75 70.49,101.75 69.25,102.99 69.25,113.26 68.26,114.25 65.75,114.25 65.2,113.7 J8.17
  BOTTOM w0.25: v1(76,82.5) v1(62.5,82.5) 54.5,82.5 52.74,84.26 41.24,84.26 40.25,85.25 8.01,85.25 7.75,84.99 7.75,79.49 6.5,78.24 v1(6.5,77)
PIO0_21-WAKEUP: length 126.6
  TOP w0.25: R16.2 v1(6.5,69) ; J8.19 v1(65.23,114.98) ; D1.A v1(9.5,122.75)
  BOTTOM w0.25: 8.75,109.5 35.74,109.5 36.5,110.26 36.5,115.39 40.06,118.95 42.7,118.95 43,119.25 54,119.25 58.27,114.98 v1(65.23,114.98) ; 8.75,109.5 8.75,121.39 9.5,122.14 v1(9.5,122.75) ; 8.75,109.5 6,106.75 6,81.5 4.25,79.75 4.25,71.25 v1(6.5,69)
PIO0_22: length 113.8
  TOP w0.25: R153.2 v1(100,67) ; v1(82,57.75) 82,59 83.5,60.5 v1(83.5,67) 83.5,80.75 82.75,81.5 82.75,90.65 83.5,91.4 83.5,105.25 80.75,108 v1(80.75,114.75) ; v1(65.25,112.75) 64.94,112.44 J8.15
  BOTTOM w0.25: v1(65.25,112.75) 68.5,112.75 69.25,113.5 70.51,113.5 71.01,114 80,114 v1(80.75,114.75) ; v1(82,57.75) 75.5,57.75 74.75,58.5 68.08,58.5 J13.5 ; v1(100,67) v1(83.5,67)
RDM_RESETN: length 120.7
  TOP w0.25: J11.10 45.46,119.96 v1(44,118.5) 43.39,118.5 43,118.11 D4.C ; R10.2 v1(6.5,80) ; J8.13 65.16,111.16 v1(65.25,111.25) ; v1(67,111.25) 67,101.49 66,100.49 R110.2
  BOTTOM w0.25: v1(67,111.25) v1(65.25,111.25) 56,111.25 55.25,112 55.25,115.44 54.44,116.25 46.25,116.25 v1(44,118.5) 40.25,118.5 36.95,115.2 36.95,109.95 36,109 9.01,109 6.5,106.49 v1(6.5,80)
RSTN_BOARDS: length 256.4
  TOP w0.25: v1(8.5,84.5) 8,84 R11.2 ; v1(80.5,100.5) v1(80.5,81.75) v1(80.5,73.5) 80.5,56.99 83.5,53.99 83.5,50.25 81.75,48.5 v1(81.75,42.5) ; R147.1 v1(100,105.25) ; JP37.1 69.5,8.5 77.25,16.25 v1(77.25,34.5) v1(77.25,42.5) ; R146.1 v1(100,73.5) ; R148.1 v1(100,34.5)
  BOTTOM w0.25: v1(80.5,81.75) 54.5,81.75 52.5,83.75 41.01,83.75 40.01,84.75 9.36,84.75 9.11,84.5 v1(8.5,84.5) ; v1(100,34.5) v1(77.25,34.5) ; v1(100,73.5) v1(80.5,73.5) ; v1(80.5,100.5) 80.5,102.5 83.25,105.25 v1(100,105.25) ; v1(81.75,42.5) v1(77.25,42.5)
SENSOR_I2C_SCL: length 28.7
  TOP w0.2: v1(62.75,71.25) 63.45,70.55 U6.5
  TOP w0.25: U8.1 v1(72.5,68.02) ; U7.8 67.37,71.13 67.25,71.25 v1(67.25,71.5)
  BOTTOM w0.25: 67.25,72 67.5,72.25 72.74,72.25 73.75,71.24 73.75,69.99 72.52,68.76 72.52,68 ; 67.25,72 63.5,72 v1(62.75,71.25) ; 67.25,72 v1(67.25,71.5) ; 72.52,68 72.5,67.98 72.5,65.5 74.2,63.8 J13.12 J13.14 ; 72.52,68 v1(72.5,68.02)
SENSOR_I2C_SDA: length 26.3
  TOP w0.2: v1(63.75,71.25) 63.85,71.15 U6.4
  TOP w0.25: v1(68.75,71.5) 68.75,70.89 68.62,70.76 U7.7 ; U8.6 v1(72.5,69.98)
  BOTTOM w0.25: 68.75,71.49 67.76,70.5 66.96,70.5 66.28,71.18 65.72,71.18 65.04,70.5 64.5,70.5 v1(63.75,71.25) ; 68.75,71.49 v1(68.75,71.5) ; 68.75,71.49 68.76,71.5 70.51,71.5 70.76,71.75 72.48,71.75 73.07,71.16 73.07,70.55 v1(72.5,69.98) 71.75,69.23 71.75,63.69 71.66,63.6 J13.10 J13.8
SENSOR_INT: length 43.7
  TOP w0.25: 71.51,65.25 76.26,65.25 76.75,65.74 76.75,69.25 76.5,69.5 R165.2 v1(76,70.5) ; 71.51,65.25 71.5,65.25 ; 71.51,65.25 70.26,64 64.25,64 ; 64.25,64 R163.2 62.25,65.5 61,66.75 R26.2 ; 64.25,64 64.04,63.79 J13.4 62.91,61.41 62.91,59.09 63.25,58.75 65.99,58.75 66.5,58.24 66.5,57.25 66.75,57 U29.2 ; R164.2 71.25,72.5 v1(71.75,73)
  BOTTOM w0.25: v1(71.75,73) 72.74,73 75.24,70.5 v1(76,70.5)
SENSOR_VDD: length 60.6
  TOP w0.2: U29.5 66.24,56.25 ; U29.5 65.6,55.61 ; U29.5 64.96,56.25 ; 64.05,55.59 R229.1 64.79,54.75 ; v1(63.75,56) 64.25,56 64.3,55.95 ; 64.96,54.75 R25.1 65.7,55.59
  TOP w0.25: v1(72.25,71) 72.25,72.25 73,73 C87.1 73.7,72.24 74,71.94 C17.2 U8.5 74,69.25 73.75,69 71.5,69 71.13,68.63 U7.4 ; v1(66,70.5) 66,70.25 ; 66,70.25 65.75,70.25 65.48,69.98 U6.1 ; 66,70.25 C14.2 ; v1(61,71) R26.1 61.76,69.8 62.06,69.5 R166.2 ; v1(66.25,66.5) C15.2 67.25,66.88 67.37,67 U7.1
  BOTTOM w0.5: v1(66.25,66.5) 66.25,68.5 66,68.75 ; J13.2 59.54,62.54 59.5,62.5 ; 61,68.75 v1(61,71) ; 61,68.75 59.5,67.25 59.5,62.5 ; 61,68.75 66,68.75 ; 59.5,62.5 59.5,58.25 61.75,56 v1(63.75,56) ; 66,68.75 70,68.75 v1(72.25,71) ; 66,68.75 v1(66,70.5)
SYS_5V0: length 31.3
  TOP w0.2: 45,111.38 C4.1 ; C4.1 44.36,112 ; C4.1 45,112.62 ; 32.36,111 C1.1 ; C1.1 33,110.38 ; C1.1 33,111.62 ; Q12.D 15.89,15.02 ; Q12.D 15,15.81 ; Q12.D 14.11,15.02 ; 13.41,40.05 L6.2 14,39.46 ; 13.12,14.5 C83.1 12.5,15.14
  TOP w0.25: v1(32,111.75) 31.8,111.95 U1.3 ; v1(32,110.25) 31.8,110.05 U1.1 ; C55.1 15.06,39.5 14.51,40.05 L6.2 ; v1(44,111.25) 43.8,111.05 U3.1 ; U3.3 43.8,112.95 v1(44,112.75) ; U4.5 52.1,105.54 52.25,105.69 C6.2 C7.1 v1(54.25,106.25) ; 12.25,16.25 10,16.25 4.75,11 R65.1
  vias: v1(11.5,39.25) v1(12.5,39.25) v1(13.25,16.5) v1(14.25,16.5) v1(15.25,16.5) v1(16.25,16.5)
USB_1V5: length 8.8
  TOP w0.2: C2.1 27.37,110.5 ; C2.1 26.75,109.86 ; C2.1 26.13,110.5 ; J5.1 28.23,108.18 ; J5.1 29.37,107.04 ; J5.1 28.23,105.9 ; J5.1 27.09,107.04 ; 28.3,109.36 U1.5 ; U1.5 27.46,110.05 ; U1.5 29.14,110.05
USB_3V0: length 9.7
  TOP w0.25: J4.4 41.5,107.04 41.5,109.75 41.25,110 39.5,110 39,110.5 39,110.92 ; U3.5 39.51,111.05 39.38,110.92 39,110.92 ; 39,110.92 C5.1
USB_DM: length 38.1
  TOP w0.25: U12.1 32.45,6.35 32.39,6.29 ; 49.25,19.86 49,20.11 U9.35
  TOP w0.35: 32.39,6.29 v1(32.2,6.1) 32.2,5.65 32.35,5.5 J33.2 32.35,4.12 ; v1(49.25,19.25) 49.25,19.86
  BOTTOM w0.35: v1(32.2,6.1) 32.45,5.85 32.45,3.82 33.32,2.95 39.26,2.95 51.51,15.2 51.51,16.74 50.75,17.5 49.37,17.5 49.02,17.85 49.02,18.39 49.25,18.62 v1(49.25,19.25)
USB_DP: length 36.2
  TOP w0.25: 48.25,19.86 48.5,20.11 U9.34 ; 32.95,6.35 U12.2
  TOP w0.35: v1(48.25,19.25) 48.25,19.86 ; 32.95,6.35 v1(33.2,6.1) 33.2,5.65 33,5.45 J33.3 33,4.12
  BOTTOM w0.35: v1(48.25,19.25) 48.25,18.61 48.47,18.39 48.47,17.62 49.14,16.95 50.52,16.95 50.96,16.51 50.96,15.43 39.03,3.5 33.55,3.5 33,4.05 33,5.9 v1(33.2,6.1)
VIO: length 68.3
  TOP w0.2: 15.66,119.4 R2.1 ; R2.1 16.5,120.14 ; R2.1 16.5,118.66 ; R2.1 17.34,119.4 ; 14.5,118.66 R1.1 ; R1.1 15.34,119.4 ; R1.1 14.5,120.14 ; R1.1 13.66,119.4 ; 12.5,118.88 C3.1 13.14,119.5
  TOP w0.25: R31.1 v1(61,83.5) ; J11.1 52.61,122.39 53.5,121.5 v1(53.5,118.5) C12.1 ; v1(56.25,66.75) C73.1 55.25,67.25 55,67.5 U24.7 ; R23.2 v1(50.5,115) ; R6.1 v1(5.5,72) ; U21.1 70.69,78.25 70.94,78.5 C68.1 v1(71.5,79.5) ; R32.1 v1(66,83.5) ; R8.1 v1(5.5,56) ; R98.1 v1(54.39,76) 54.64,75.75 55,75.75 55.25,76 U22.10 ; R35.1 v1(69,83.5) ; v1(70.25,76.45) 70,76.7 U21.15 ; R19.2 R18.1 50,109.25 v1(49.75,109.5) ; U23.5 74.05,79.89 74,79.94 R99.1 v1(73,80.5) ; L7.2 v1(59,92.5) ; R22.2 v1(44.5,115) ; v1(65,105) 64.82,104.82 J8.3 ; R13.2 v1(56.25,100.25) ; U22.1 59.19,78.25 59.44,78.5 C71.1 v1(60,79.5) ; J8.5 64.92,106.08 v1(65,106) ; R5.1 v1(5.5,80) ; R33.1 v1(63.5,83.5) ; 12.65,120.1 U2.1 13.25,120.5 13.5,120.25 13.5,119.75 ; Q2.G v1(86.23,114.75) ; R93.1 v1(62,78) ; R34.1 v1(71.5,83.5) ; R7.1 v1(5.5,64) ; R36.1 v1(74,83.5)
  IN2 w0.2: 55.26,62.54 J16.1 ; J16.1 56.5,63.78 ; J16.1 56.5,61.3 ; J16.1 57.74,62.54 ; J13.1 62.74,60 ; J13.1 61.5,61.24 ; J13.1 61.5,58.76 ; J13.1 60.26,60 ; 51.5,61.3 J22.1 52.74,62.54
  vias: v1(17.75,119.5) v1(17.75,118.5)
VREF_MCULINK: length 45.2
  TOP w0.25: v1(40,26) 41,27 U9.17 ; v1(40,26) 40,26.74 39.74,27 C44.1 ; v1(40,26) C45.1 ; v1(40,26) 40,25.25 39.75,25 R62.2 ; R40.2 v1(64.5,26.75) ; v1(32.5,27) 32.48,27.02 U10.C
  BOTTOM w0.25: v1(32.5,27) 32.5,26.39 33.14,25.75 40,25.75 ; 40,25.75 v1(40,26) ; 40,25.75 40.79,25.75 41.29,25.25 41.75,25.25 42.75,24.25 48.62,24.25 49.07,24.7 52.93,24.7 53.38,24.25 57.5,24.25 60,26.75 v1(64.5,26.75)
N56442: length 2.2
  TOP w0.25: R89.1 U21.4
N3578794: length 5
  TOP w0.25: U21.9 65,77.75 64.75,78 R93.2 64,77.25 64.52,76.73 Q10.D
N3581084: length 3.2
  TOP w0.25: R87.1 69.25,81.5 69,81.25 69,80.5 68.75,80.25 U21.3
N3594293: length 6.3
  TOP w0.25: U22.9 52.75,77.75 52.5,77.5 R98.2 52.5,75.46 52.48,75.44 Q11.D
N3596543: length 2.5
  TOP w0.25: U22.3 57.25,80.19 58,80.94 R94.1
N3596557: length 2.3
  TOP w0.25: R96.1 57,80.94 56.75,80.69 U22.4
N3596571: length 2.3
  TOP w0.25: U22.5 56.25,80.69 56,80.94 R95.1
N3596575: length 2.5
  TOP w0.25: U22.6 55.75,80.19 55,80.94 R97.1
N4897644: length 1.4
  TOP w0.25: D17.C R90.2
N4898305: length 2.4
  TOP w0.25: U21.5 67.75,80.39 67.25,80.89 R90.1
N4898918: length 2.3
  TOP w0.25: U21.12 67.75,75.31 68,75.06 R91.2
N4953028: length 9
  TOP w0.25: U21.6 67.25,80.25 66.75,80.75 65.5,80.75 v1(64.75,80) ; U21.10 65.95,76.7 v1(65.75,76.5)
  BOTTOM w0.25: v1(65.75,76.5) 64.75,77.5 v1(64.75,80)
N12265657: length 4.5
  TOP w0.25: J14.7 87.26,42.73 87.5,42.49 C18.1 86.72,41.05 86.42,40.75 R29.2
N12266589: length 4.5
  TOP w0.25: J18.7 87.26,81.73 87.5,81.49 C19.1 86.72,80.05 86.42,79.75 R30.2
N12275396: length 2.8
  TOP w0.25: J14.2 99.96,42.73 100,42.69 R148.2
N12275400: length 2.8
  TOP w0.25: J14.3 97.42,42.73 97.5,42.65 R149.2
N12275404: length 2.9
  TOP w0.25: J14.4 94.88,42.73 95,42.61 R150.2
N12275408: length 2.9
  TOP w0.25: J14.5 92.34,42.73 92.5,42.57 R151.2
N12275412: length 2.9
  TOP w0.25: R152.2 90,42.53 89.8,42.73 J14.6
N12276056: length 2.7
  TOP w0.25: R155.1 J15.1
N12276068: length 2.7
  TOP w0.25: R156.1 100,22.17 99.96,22.13 J15.2
N12276080: length 2.7
  TOP w0.25: R157.1 97.5,22.21 97.42,22.13 J15.3
N12276104: length 2.7
  TOP w0.25: J15.4 94.88,22.13 95,22.25 R158.1
N12276108: length 2.8
  TOP w0.25: J15.5 92.34,22.13 92.5,22.29 R159.1
N12276112: length 2.8
  TOP w0.25: J15.6 89.8,22.13 90,22.33 R160.1
N12276934: length 2.8
  TOP w0.25: R146.2 100,81.69 99.96,81.73 J18.2
N12276966: length 2.8
  TOP w0.25: J18.3 97.42,81.73 97.5,81.65 R138.2
N12276998: length 2.9
  TOP w0.25: R139.2 95,81.61 94.88,81.73 J18.4
N12277030: length 2.9
  TOP w0.25: J18.5 92.34,81.73 92.5,81.57 R140.2
N12277038: length 2.9
  TOP w0.25: R141.2 90,81.53 89.8,81.73 J18.6
N12277309: length 2.7
  TOP w0.25: R154.1 J17.1
N12277341: length 2.7
  TOP w0.25: J17.2 99.96,61.13 100,61.17 R153.1
N12277373: length 2.7
  TOP w0.25: R135.1 97.5,61.21 97.42,61.13 J17.3
N12277413: length 2.7
  TOP w0.25: J17.4 94.88,61.13 95,61.25 R136.1
N12277445: length 2.8
  TOP w0.25: J17.5 92.34,61.13 92.5,61.29 R137.1
N12277469: length 2.8
  TOP w0.25: J17.6 89.8,61.13 90,61.33 R134.1
N12278499: length 2.7
  TOP w0.25: R128.1 J21.1
N12278559: length 2.8
  TOP w0.25: R147.2 100,111.69 99.96,111.73 J20.2
N12278563: length 2.7
  TOP w0.25: R129.1 100,91.17 99.96,91.13 J21.2
N12278623: length 2.8
  TOP w0.25: R142.2 97.5,111.65 97.42,111.73 J20.3
N12278627: length 2.7
  TOP w0.25: R130.1 97.5,91.21 97.42,91.13 J21.3
N12278695: length 2.9
  TOP w0.25: R143.2 95,111.61 94.88,111.73 J20.4
N12278699: length 2.7
  TOP w0.25: J21.4 94.88,91.13 95,91.25 R131.1
N12278759: length 2.9
  TOP w0.25: R144.2 92.5,111.57 92.34,111.73 J20.5
N12278763: length 2.8
  TOP w0.25: J21.5 92.34,91.13 92.5,91.29 R132.1
N12278819: length 2.9
  TOP w0.25: J20.6 89.8,111.73 90,111.53 R145.2
N12278823: length 2.8
  TOP w0.25: J21.6 89.8,91.13 90,91.33 R133.1
N12278835: length 4.5
  TOP w0.25: J20.7 87.26,111.73 87.5,111.49 C20.1 86.72,110.05 86.42,109.75 R37.2
N12295606: length 1.5
  TOP w0.25: U7.2 68.62,67.38 68.75,67.25 C16.2
N12315434: length 2.2
  TOP w0.25: U11.4 30.45,14.89 30.5,14.94 C52.1
N12315580: length 6.8
  TOP w0.25: 31.7,4.12 J33.1 31.7,5.45 31.25,5.9 30.8,5.9 30.5,6.2 BD1.1 31.2,6.95 31.5,7.25 31.5,8.25 31.81,8.56 U12.6
N12322367: length 3.5
  TOP w0.25: J23.3 69.44,3.6 69.5,3.66 JP37.2
N12329989: length 50.7
  TOP w0.25: 36.5,71.42 36.52,71.4 36.52,71.33 ; R78.1 29,63 TP5.1 v1(30.5,63.5) R75.1 ; R231.2 v1(21.75,67)
  TOP w0.5: 30.5,68 22.75,68 v1(21.75,67) ; 30.5,68 35.5,68 36.5,67 37.5,67 Q7.S ; 30.5,68 v1(30.5,67) ; Q27.S 36.83,71.02 36.5,71.35 v1(36.5,72) ; v1(30.5,67) 30.5,66.25 30.75,66 Q14.D ; v1(30.5,67) R224.2 ; v1(18.75,61) R67.2
  BOTTOM w0.5: v1(21.75,67) 21.75,64 v1(18.75,61) ; v1(36.5,72) 31.26,72 30.5,71.24 v1(30.5,67) v1(30.5,63.5)
N12329993: length 5.4
  TOP w0.25: U17.3 34.85,62.85 34.5,62.5 34.5,62 34,61.5 C62.1 R77.2 R75.2
N12330033: length 6.4
  TOP w0.25: U17.1 37.45,61.95 36.5,61 36.5,60.25 ; 36.5,60.25 36.4,60.15 U17.4 ; 36.5,60.25 36.5,58.75 36.25,58.5 R76.1
N12330403: length 7.1
  TOP w0.25: TP6.1 R83.1 ; R83.1 25,55.75 24.77,55.98 Q9.S ; R83.1 25.56,54.5 25.96,54.9 U19.5
N12330433: length 2
  TOP w0.25: R78.2 29,60.44 28.82,60.26 U19.2
N12330505: length 6.1
  TOP w0.25: R82.1 C67.2 R85.2 29.3,53.7 28.82,54.18 U19.7
N12330553: length 6.8
  TOP w0.25: U19.6 28.19,54.25 27.7,53.76 R85.1 C67.1 R81.2
N12330797: length 6.3
  TOP w0.25: R80.1 v1(26,59.5) ; U19.1 29.48,59.98 v1(29.75,60.25)
  BOTTOM w0.25: v1(29.75,60.25) 29,59.5 v1(26,59.5)
N12330801: length 2.2
  TOP w0.25: R80.2 23.44,59.5 23.26,59.32 23.26,59.05 23.48,58.83 Q9.G
N12330825: length 6.5
  TOP w0.25: R79.2 28,60.44 28.18,60.26 U19.3 28.18,57.43 27.75,57 Q9.D
N12331089: length 22.2
  TOP w0.25: R79.1 28,63 TP4.1 v1(26.5,63.5)
  TOP w0.5: R73.1 v1(26.5,65) ; Q22.D 22.14,70 22.5,70.36 22.5,70.86 22.66,71.02 Q25.S 26.27,71.02 26.5,71.25 v1(26.5,72) ; R224.1 v1(26.5,67)
  BOTTOM w0.5: v1(26.5,72) v1(26.5,67) v1(26.5,65) v1(26.5,63.5)
N12331509: length 7.9
  TOP w0.5: Q14.S 33.52,66.02 33.5,66 ; 33.5,66 32.82,66 32.5,65.68 32.5,65.25 32.25,65 R73.2 ; 33.5,66 Q7.D
N12333663: length 10.2
  TOP w0.25: 38.5,65 38.5,64.5 38.75,64.25 R228.1 ; 38.5,65 38.5,67 38.75,67.25 40.25,67.25 40.5,67 40.5,66.25 40.75,66 R72.1 43,66 ; 38.5,65 38.48,64.98 Q7.G
N12334532: length 2.6
  TOP w0.25: Q8.D 39.48,64.77 39.75,64.5 R228.2
N12369229: length 6.3
  TOP w0.25: 49,18.25 48.19,18.25 48,18.06 R63.2 ; 49,18.25 R64.1 ; 49,18.25 49.4,18.25 50,18.85 50,19.82 49.5,20.32 U9.36
N12373644: length 5.9
  TOP w0.25: 60.75,26.5 61,26.75 R40.1 ; 60.75,26.5 U9.58 ; 60.75,26.5 60.75,25.25 61,25 R41.2
N12374436: length 1.6
  TOP w0.25: R44.2 2.5,26.75 2.18,27.07 D8.A
N12374792: length 1.6
  TOP w0.25: D9.A 2.18,15.07 2.5,14.75 R45.2
N12374932: length 1.6
  TOP w0.25: D10.A 2.18,18.07 2.5,17.75 R54.2
N12375074: length 14.4
  TOP w0.25: R57.2 9.95,47.95 9.75,47.75 6.5,47.75 5.75,48.5 2.25,48.5 2,48.25 2,44.59 J31.7
N12375164: length 1.6
  TOP w0.25: R56.2 2.5,23.75 2.18,24.07 D11.A
N12375264: length 1.6
  TOP w0.25: D12.A 2.18,21.07 2.5,20.75 R58.2
N12375326: length 1.6
  TOP w0.25: R59.2 2.5,32.5 2.18,32.82 D13.A
N12375380: length 1.6
  TOP w0.25: R61.2 2.5,29.75 2.18,30.07 D14.A
N12381948: length 1.5
  TOP w0.25: U8.3 75.06,68.02 75.54,68.5 R165.1
N12381957: length 1.6
  TOP w0.25: U7.6 69.88,70.84 70.25,71.21 R164.1
N12382534: length 1.5
  TOP w0.2: R163.1 64.25,68.01 U6.8
N12393061: length 13.7
  TOP w0.25: 51.25,20 51,20.25 U9.39 ; C43.1 53.86,18.75 54,18.89 U9.45
  TOP w0.5: 52,18.75 C42.1 C41.1 52,15.75 52.25,15.5 L4.2 ; 52,18.75 C43.1 ; 52,18.75 52,19.25 51.25,20
N12393117: length 9.7
  TOP w0.25: 56,19.48 55.5,19.98 U9.48
  TOP w0.5: L4.1 55.75,15.75 56,16 56,19.48 55.55,19.91
N12422072: length 35.7
  TOP w0.5: BAT3.1 22.9,114.85 24.5,113.25 ; 24.5,113.25 24.5,105.25 25.25,104.5 J5.3 ; 24.5,113.25 34.26,113.25 36.1,115.09 BAT3.3
N12422390: length 12.5
  BOTTOM w0.2: BAT2.3 11.77,90.04 ; BAT2.3 11.77,87.76 ; BAT2.3 10.63,88.9 ; BAT2.3 12.91,88.9 ; BAT2.2 9.23,90.04 ; BAT2.2 9.23,87.76 ; BAT2.2 10.37,88.9 ; J4.6 43.91,103.23 ; J4.6 42.77,104.37 ; J4.6 42.77,102.09 ; J4.6 41.63,103.23
N12442192: length 12.5
  TOP w0.25: C9.1 R15.1 8.73,75 J37.1 ; C9.1 R6.2 ; C9.1 3.8,75 ; 3.8,75 SW2.1 ; 3.8,75 SW2.3
N12442224: length 8.8
  TOP w0.25: 3.8,83 SW1.1 ; 3.8,83 C8.1 ; 3.8,83 SW1.3 ; R5.2 C8.1 ; C8.1 R11.1 R10.1
N12449351: length 7.8
  TOP w0.25: 3.8,67 SW3.1 ; 3.8,67 SW3.3 ; 3.8,67 C10.1 ; R16.1 C10.1 ; C10.1 R7.2
N12450169: length 7.8
  TOP w0.25: C11.1 3.8,59 ; C11.1 R21.1 ; C11.1 R8.2 ; 3.8,59 SW4.1 ; 3.8,59 SW4.3
N12453362: length 1.9
  TOP w0.25: U2.6 10.5,120.5 10.3,120.3 D1.C
N12454206: length 1.8
  TOP w0.25: R1.2 U2.2
N12454210: length 4.6
  TOP w0.25: R2.2 16.5,121.5 16.25,121.75 13.75,121.75 13.5,121.5 U2.3
N12480389: length 5.5
  TOP w0.2: 13.86,6 C53.1 14.5,6.62 ; 10.76,7.3 L5.1 ; L5.1 11.5,6.66 ; L5.1 12.24,7.3
  TOP w0.25: 13,6 13.7,5.3 J34.1 13.7,4.12
N12480952: length 5.6
  TOP w0.2: 13.36,8.56 D19.A ; D19.A 13.36,10.44 ; D19.A 12.57,9.5 ; D19.A 14.15,9.5 ; 10.76,8.7 L5.2 ; L5.2 11.5,9.34 ; L5.2 12.24,8.7
N12522256: length 2.8
  TOP w0.25: R115.1 74,96.25 73.75,96.5 U28.5
N12522264: length 3
  TOP w0.25: R112.2 R114.1 74,97.5 73.75,97.25 U28.4
N12522562: length 3
  TOP w0.25: U25.4 69.75,97.25 70,97.5 R105.1 R104.2
N12522860: length 3
  TOP w0.25: R108.2 R110.1 66,97.5 65.75,97.25 U27.4
N12527022: length 2
  TOP w0.25: U26.4 61.75,97.25 62,97.5 R109.1
N12533780: length 1.3
  TOP w0.25: R100.1 76,79.94 75.95,79.89 U23.4
N12537164: length 2.3
  TOP w0.25: R92.2 67,75.06 67.25,75.31 U21.11
N12627127: length 1.6
  TOP w0.25: R65.2 2.5,11.5 2.18,11.82 D16.A
N12627699: length 9.9
  TOP w0.2: 15.5,10.88 R161.1 16.14,11.5 ; 18.36,8.56 D18.C ; D18.C 18.36,10.44 ; D18.C 17.57,9.5 ; D18.C 19.15,9.5 ; D19.C 17.43,9.5 ; D19.C 16.64,10.44 ; D19.C 16.64,8.56 ; D19.C 15.85,9.5
  TOP w0.25: Q12.S 16.02,12.52 15.75,12.25 15.71,12.25 15.5,12.04 R161.1
N12627791: length 5.7
  TOP w0.25: C83.2 12.5,12.75 ; 12.5,12.75 12.92,12.75 13.17,13 13.96,13 Q12.G 13.98,12.56 14.5,12.04 R161.2 ; 12.5,12.75 11.69,12.75 11.5,12.94 R162.1
N12648217: length 7.3
  TOP w0.25: J3.2 53.5,98.25 52.8,98.95 R12.1 R17.1
N12648225: length 1.8
  TOP w0.25: R12.2 52.46,100.55 52.76,100.25 R13.1
N12648461: length 4.6
  TOP w0.25: U4.3 48.69,102.3 48.25,101.86 R20.2 48.69,100.25 48.99,100.55 R17.2
N12648493: length 6.1
  TOP w0.25: U4.4 51.2,102.3 50.75,102.75 50.75,104.25 ; 50.75,104.25 R19.1 ; 50.75,104.25 50.7,104.2 U4.1
N12652986: length 2.3
  TOP w0.25: R31.2 61,86.06 61.15,86.21 J19.1
N12653032: length 2.3
  TOP w0.25: J19.3 63.69,86.25 63.5,86.06 R33.2
N12653078: length 2.3
  TOP w0.25: R32.2 66,86.06 66.23,86.29 J19.5
N12653124: length 2.3
  TOP w0.25: J19.7 68.77,86.29 69,86.06 R35.2
N12653170: length 2.3
  TOP w0.25: J19.9 71.31,86.25 71.5,86.06 R34.2
N12653192: length 2.3
  TOP w0.25: R36.2 74,86.06 73.85,86.21 J19.11
N12655772: length 1.7
  TOP w0.25: D2.C Q1.D
N12655780: length 1.6
  TOP w0.25: R3.2 90.34,121.5 90.66,121.82 D2.A
N12655848: length 1.7
  TOP w0.25: D3.C Q2.D
N12655856: length 1.6
  TOP w0.25: R9.2 86.29,121.5 86.61,121.82 D3.A
N12656530: length 3.2
  TOP w0.2: U6.7 63.85,67.44 63.61,67.2 62.88,67.2
  TOP w0.25: 62.88,67.2 62.8,67.2 62.5,67.5 R166.1
N12790182: length 5.4
  TOP w0.5: Q20.D 15.48,71.5 15.7,71.72 C88.1 15.7,73.88 15.15,74.43 U30.5
N12790214: length 1.7
  TOP w0.2: U30.4 14.41,76.95 14.36,77 C89.1
N12795272: length 3.1
  TOP w0.25: R67.1 15.7,59.03 15.48,58.81 Q16.D
N12795276: length 3.1
  TOP w0.25: Q17.D 15.48,64.81 15.7,65.03 R71.1
N12795416: length 3.3
  TOP w0.25: D20.A 18.62,56.9 18.54,56.98 Q16.G 17.52,55.52 R230.2
N12796249: length 4
  TOP w0.5: Q22.S Q20.S
N12796253: length 26.4
  TOP w0.2: 39.48,69.25 39.48,69.21 39.46,69.19
  TOP w0.25: Q20.G Q22.G Q25.G Q24.G Q26.G Q27.G 39.25,68.98 39.46,69.19 ; 39.48,69.25 Q21.D R66.1 43,70
N12796853: length 4
  TOP w0.5: Q25.D Q24.D
N12797165: length 4
  TOP w0.5: Q26.D Q27.D
N12815289: length 25
  TOP w0.25: v1(67.5,89) 67.5,84 68.25,83.25 R89.2
  BOTTOM w0.25: 56.5,88.25 57.75,88.25 58.5,89 v1(67.5,89) ; 56.5,88.25 52.75,88.25 J36.4 ; 56.5,88.25 56.56,88.31 J36.8
N12815293: length 31.5
  TOP w0.25: R87.2 70,90.75 69.25,91.5 56,91.5 J36.6
  BOTTOM w0.25: J36.6 52.79,90.75 50.17,90.75 J36.2
N12892834: length 3.5
  TOP w0.25: C13.2 R25.2 67.3,55.26 ; 67.3,55.26 67.3,55.51 ; 67.3,55.26 67.4,55.36 U29.1
N12892932: length 2.2
  TOP w0.25: R27.2 64,57.54 64.21,57.75 U29.4
N12893707: length 12.2
  TOP w0.25: R27.1 v1(62,57) 62,56 62.45,55.55 R229.2
  BOTTOM w0.25: J13.6 65.25,61.21 65.25,58 64.25,57 v1(62,57)
N12901647: length 1.6
  TOP w0.25: R71.2 R231.1

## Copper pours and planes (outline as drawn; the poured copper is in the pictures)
3V3 on TOP: 29.5,15.75 29.5,12.25 25.75,12.25 25.75,15.75
3V3 on TOP: 38.75,44.25 38.75,40.75 42.5,40.75 42.5,44.25
3V3 on IN2: 63.5,95 77.75,95 77.75,75.25 74,71.5 58.75,71.5 50.25,63 50.25,59.25 63.25,46.25 63.25,10.5 4,10.5 4,55.25 33.75,55.25 44.72,66.22 44.74,71.74 48.25,75.25 55,75.25 55,77 69.5,77 69.5,75.75 70.75,75.75 70.75,77.5 75,81.75 75,90.76 74.26,91.5 63.5,91.5
GND on TOP (solid shape): 34.24,118.1 34.44,117.84 34.44,117.75 34.5,117.6 34.65,117.54 35.64,117.54 35.64,115.28 34.07,113.72 24.69,113.72 23.36,115.04 23.36,117.54 24.35,117.54 24.5,117.6 24.56,117.75 24.56,117.84 24.76,118.1 25.05,117.93 29.5,114.78 33.95,117.93
